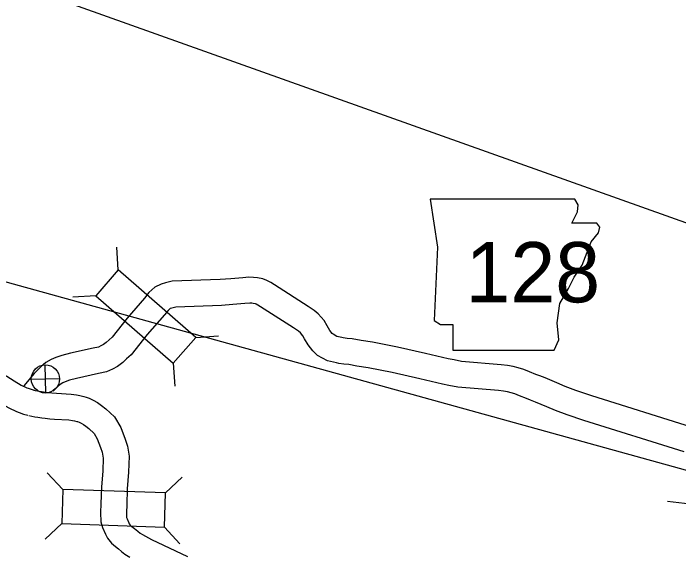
# Model space of a CAD drawing. Extents: x 1373862 to 1377080, y 1164775 to 1170415.
# Drawn here: x 1374204.1 to 1374281, y 1170088.2 to 1170151.1 of the extents above; entities that cross this region are included whole.
import ezdxf

# ---------------------------------------------------------------- set-up
doc = ezdxf.new("R2010")
doc.units = 0
doc.layers.add('1', color=7, linetype='Continuous')
doc.layers.add('Default', color=7, linetype='Continuous')

msp = doc.modelspace()

# ---------------------------------------------------------------- linework, layer by layer
at = {"layer": '1'}
for p in [(1374172.843, 1170165.768), (1374199.554, 1170121.066)]:
    msp.add_line(p, (1374640.758, 1169998.763), dxfattribs=at)
at = {"layer": 'Default'}
for p, q in [((1374216.221, 1170121.408), (1374216.04, 1170124.042)), ((1374213.619, 1170118.422), (1374210.985, 1170118.242)), ((1374225.177, 1170113.603), (1374227.811, 1170113.783)), ((1374207.832, 1170107.171), (1374207.757, 1170110.426)), ((1374222.575, 1170110.617), (1374222.756, 1170107.983)), ((1374206.167, 1170108.761), (1374209.422, 1170108.836)), ((1374209.81, 1170096.021), (1374208.005, 1170097.948)), ((1374221.683, 1170095.629), (1374223.61, 1170097.433)), ((1374282.313, 1170094.298), (1374279.696, 1170094.642)), ((1374209.679, 1170092.063), (1374207.752, 1170090.258)), ((1374221.553, 1170091.671), (1374223.357, 1170089.744))]:
    msp.add_line(p, q, dxfattribs=at)
for points in [[(1374252.275, 1170129.609), (1374253.112, 1170124.026), (1374252.74, 1170115.558), (1374253.484, 1170115.093), (1374254.88, 1170115.093), (1374254.88, 1170112.116), (1374266.604, 1170112.116), (1374267.162, 1170113.325), (1374266.976, 1170115.279), (1374267.255, 1170117.512), (1374268.279, 1170119.28), (1374268.93, 1170120.583), (1374269.861, 1170121.979), (1374270.419, 1170123.467), (1374270.884, 1170124.677), (1374271.722, 1170125.701), (1374271.908, 1170126.352), (1374271.536, 1170126.817), (1374268.651, 1170126.817), (1374269.302, 1170128.12), (1374269.396, 1170128.957), (1374269.01, 1170129.6)], [(1374225.177, 1170113.603), (1374216.221, 1170121.408), (1374213.619, 1170118.422), (1374222.575, 1170110.617)], [(1374209.679, 1170092.063), (1374221.553, 1170091.671), (1374221.683, 1170095.629), (1374209.81, 1170096.021)]]:
    msp.add_lwpolyline(points, close=True, dxfattribs=at)
for points in [[(1374187.216, 1170123.846), (1374187.871, 1170122.418), (1374188.389, 1170121.499), (1374189.217, 1170120.271), (1374189.857, 1170119.303), (1374190.833, 1170118.218), (1374193.451, 1170115.716), (1374195.213, 1170113.87), (1374196.256, 1170112.833), (1374197.504, 1170112.02), (1374198.623, 1170111.407), (1374200.016, 1170110.733), (1374201.558, 1170109.972), (1374202.594, 1170109.454), (1374203.322, 1170109.103), (1374204.17, 1170108.585), (1374204.993, 1170108.095), (1374205.662, 1170107.78), (1374205.819, 1170107.715), (1374206.154, 1170107.604), (1374206.596, 1170107.477)], [(1374184.489, 1170122.595), (1374185.196, 1170121.054), (1374185.834, 1170119.922), (1374186.723, 1170118.605), (1374187.477, 1170117.464), (1374188.677, 1170116.128), (1374191.329, 1170113.594), (1374193.07, 1170111.77), (1374194.36, 1170110.487), (1374195.962, 1170109.444), (1374197.248, 1170108.739), (1374198.699, 1170108.038), (1374200.223, 1170107.286), (1374201.271, 1170106.762), (1374201.885, 1170106.465), (1374202.621, 1170106.016), (1374203.583, 1170105.443), (1374204.456, 1170105.031), (1374204.779, 1170104.9), (1374205.265, 1170104.739), (1374205.763, 1170104.594)], [(1374282.487, 1170103.237), (1374270.974, 1170106.835), (1374269.125, 1170107.45), (1374267.897, 1170107.937), (1374266.935, 1170108.344), (1374265.556, 1170108.913), (1374264.954, 1170109.142), (1374264.486, 1170109.326), (1374263.742, 1170109.613), (1374263.096, 1170109.887), (1374262.464, 1170110.083), (1374261.871, 1170110.241), (1374261.214, 1170110.366), (1374260.484, 1170110.449), (1374255.894, 1170110.822), (1374255.041, 1170110.995), (1374254.347, 1170111.136), (1374251.739, 1170111.727), (1374248.515, 1170112.483), (1374245.616, 1170113.049), (1374244.292, 1170113.25), (1374243.272, 1170113.428), (1374242.692, 1170113.483), (1374242.231, 1170113.558), (1374242.083, 1170113.586), (1374241.488, 1170113.726), (1374241.048, 1170113.963), (1374240.954, 1170114.056), (1374240.681, 1170114.414), (1374240.365, 1170114.956), (1374240.01, 1170115.576), (1374239.329, 1170116.314), (1374238.85, 1170116.704), (1374238.158, 1170117.187), (1374234.296, 1170119.671), (1374233.873, 1170119.94), (1374233.396, 1170120.195), (1374232.927, 1170120.365), (1374232.307, 1170120.497), (1374231.845, 1170120.55), (1374231.333, 1170120.56), (1374230.626, 1170120.498), (1374229.235, 1170120.395), (1374227.985, 1170120.296), (1374222.457, 1170120.092)], [(1374222.457, 1170120.092), (1374221.688, 1170119.905), (1374221.177, 1170119.779), (1374220.465, 1170119.414), (1374219.773, 1170118.784), (1374219.255, 1170118.131), (1374217.259, 1170115.841), (1374215.523, 1170113.65), (1374215.152, 1170113.321), (1374214.827, 1170113.007), (1374214.498, 1170112.766), (1374214.222, 1170112.612), (1374213.941, 1170112.488), (1374213.312, 1170112.352), (1374210.688, 1170111.781), (1374209.696, 1170111.517), (1374209.008, 1170111.268), (1374208.483, 1170111.052), (1374207.852, 1170110.683), (1374207.288, 1170110.187), (1374206.518, 1170109.435), (1374205.314, 1170108.021)], [(1374281.627, 1170100.363), (1374270.053, 1170103.979), (1374268.097, 1170104.63), (1374266.76, 1170105.161), (1374265.778, 1170105.576), (1374264.451, 1170106.123), (1374263.871, 1170106.344), (1374263.397, 1170106.531), (1374262.618, 1170106.831), (1374262.062, 1170107.066), (1374261.633, 1170107.2), (1374261.204, 1170107.314), (1374260.762, 1170107.398), (1374260.193, 1170107.463), (1374255.472, 1170107.846), (1374254.444, 1170108.055), (1374253.718, 1170108.202), (1374251.065, 1170108.804), (1374247.885, 1170109.55), (1374245.104, 1170110.093), (1374243.809, 1170110.288), (1374242.869, 1170110.453), (1374242.31, 1170110.506), (1374241.711, 1170110.603), (1374241.459, 1170110.651), (1374240.414, 1170110.896), (1374239.248, 1170111.525), (1374238.698, 1170112.067), (1374238.182, 1170112.743), (1374237.768, 1170113.455), (1374237.575, 1170113.79), (1374237.268, 1170114.124), (1374237.042, 1170114.308), (1374236.488, 1170114.694), (1374232.678, 1170117.144), (1374232.357, 1170117.349), (1374232.173, 1170117.447), (1374232.101, 1170117.473), (1374231.82, 1170117.533), (1374231.643, 1170117.554), (1374231.436, 1170117.557), (1374230.867, 1170117.508), (1374229.464, 1170117.404), (1374228.16, 1170117.3), (1374222.871, 1170117.105)], [(1374222.871, 1170117.105), (1374222.399, 1170116.99), (1374222.233, 1170116.95), (1374222.19, 1170116.927), (1374221.972, 1170116.729), (1374221.562, 1170116.212), (1374219.567, 1170113.923), (1374217.71, 1170111.579), (1374217.19, 1170111.119), (1374216.764, 1170110.706), (1374216.122, 1170110.238), (1374215.564, 1170109.925), (1374214.871, 1170109.619), (1374213.947, 1170109.42), (1374211.393, 1170108.864), (1374210.593, 1170108.651), (1374210.089, 1170108.469), (1374209.818, 1170108.357), (1374209.616, 1170108.239), (1374209.328, 1170107.986), (1374208.713, 1170107.385), (1374208.706, 1170107.377)], [(1374206.478, 1170107.505), (1374207.085, 1170107.382), (1374207.347, 1170107.348), (1374207.807, 1170107.272), (1374208.116, 1170107.232), (1374208.559, 1170107.19), (1374209.085, 1170107.147), (1374210.772, 1170107.04), (1374211.39, 1170106.964), (1374211.784, 1170106.891), (1374212.239, 1170106.781), (1374212.498, 1170106.697), (1374212.86, 1170106.567), (1374213.304, 1170106.356), (1374213.833, 1170106.056), (1374214.299, 1170105.71), (1374214.769, 1170105.337), (1374215.776, 1170104.419), (1374216.514, 1170103.179), (1374217.026, 1170101.825), (1374217.273, 1170101.019), (1374217.472, 1170099.869), (1374217.422, 1170098.019), (1374217.268, 1170096.107), (1374217.195, 1170094.251), (1374217.166, 1170093.353), (1374217.192, 1170092.773), (1374217.236, 1170092.629), (1374217.443, 1170092.139), (1374217.499, 1170092.035), (1374217.605, 1170091.899), (1374217.805, 1170091.726), (1374218.096, 1170091.494), (1374218.489, 1170091.189), (1374218.744, 1170090.976), (1374219.038, 1170090.797), (1374220.063, 1170090.243), (1374224.235, 1170088.254)], [(1374205.881, 1170104.566), (1374206.593, 1170104.421), (1374206.91, 1170104.38), (1374207.369, 1170104.304), (1374207.78, 1170104.251), (1374208.294, 1170104.202), (1374208.867, 1170104.155), (1374210.493, 1170104.052), (1374210.934, 1170103.997), (1374211.159, 1170103.956), (1374211.424, 1170103.892), (1374211.525, 1170103.859), (1374211.703, 1170103.795), (1374211.92, 1170103.691), (1374212.193, 1170103.538), (1374212.47, 1170103.331), (1374212.824, 1170103.05), (1374213.425, 1170102.502), (1374213.801, 1170101.871), (1374214.186, 1170100.852), (1374214.35, 1170100.321), (1374214.465, 1170099.652), (1374214.425, 1170098.18), (1374214.272, 1170096.286), (1374214.197, 1170094.359), (1374214.164, 1170093.335), (1374214.212, 1170092.255), (1374214.414, 1170091.601), (1374214.737, 1170090.835), (1374214.984, 1170090.381), (1374215.422, 1170089.821), (1374215.886, 1170089.42), (1374216.238, 1170089.138), (1374216.608, 1170088.85), (1374216.996, 1170088.528), (1374217.544, 1170088.194)]]:
    msp.add_lwpolyline(points, dxfattribs=at)
msp.add_circle((1374207.794, 1170108.799), 1.628, dxfattribs=at)

# ---------------------------------------------------------------- texts
msp.add_text('128', height=6.9696, dxfattribs=at).set_placement((1374256.371, 1170117.659))

doc.saveas('drawing.dxf')
